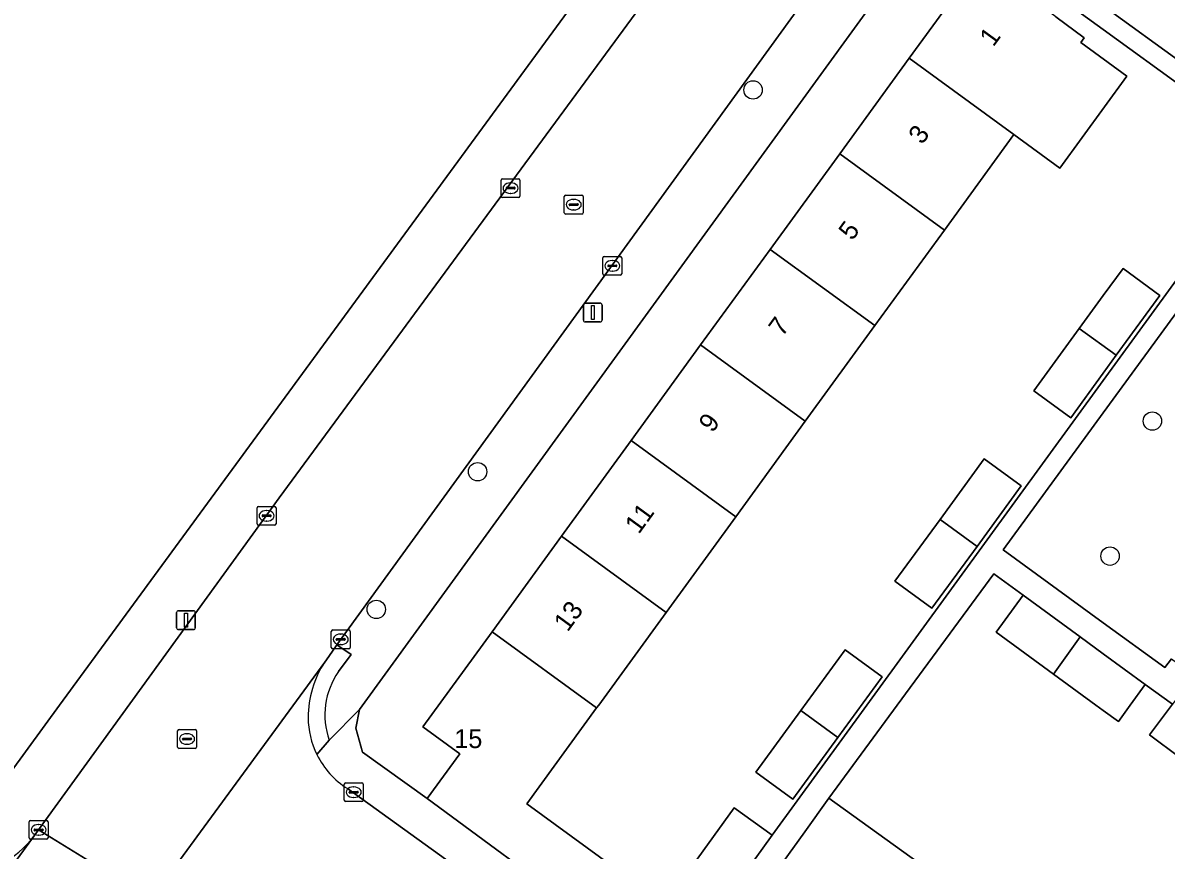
# Model space of a CAD drawing. Extents: x 160102 to 160934, y 382045 to 382923.
# Drawn here: x 160442.6 to 160503.3, y 382492.3 to 382536.2 of the extents above; entities that cross this region are included whole.
import ezdxf

# ---------------------------------------------------------------- set-up
doc = ezdxf.new("R2010")
doc.units = 0
for name, color, linetype in [('IMGEO_Boom', 7, 'Continuous'), ('IMGEO_Erf', 7, 'Continuous'), ('IMGEO_Groenvoorziening', 7, 'Continuous'), ('IMGEO_Kolk', 7, 'Continuous'), ('IMGEO_Lichtmast', 7, 'Continuous'), ('IMGEO_Pand', 7, 'Continuous'), ('IMGEO_Pand_nummerreeks', 7, 'Continuous'), ('IMGEO_Rijbaan_lokaal_open', 7, 'Continuous'), ('IMGEO_Rioolput', 7, 'Continuous'), ('IMGEO_Voetpad_open', 7, 'Continuous')]:
    doc.layers.add(name, color=color, linetype=linetype)

msp = doc.modelspace()

# ---------------------------------------------------------------- linework, layer by layer
at = {"layer": 'IMGEO_Boom'}
for centre in [(160481.4, 382532.653), (160502.606, 382515.077), (160466.767, 382512.388), (160500.358, 382507.908), (160461.385, 382505.081)]:
    msp.add_circle(centre, 0.489, dxfattribs=at)
at = {"layer": 'IMGEO_Erf'}
for points in [[(160466.307, 382588.202), (160494.827, 382565.152), (160500, 382560.972), (160503.073, 382558.488), (160500, 382554.224), (160491.895, 382542.979), (160500, 382537.111), (160512.903, 382527.769), (160513.795, 382534.731), (160510.825, 382535.221), (160511.14, 382537.129), (160511.461, 382539.075), (160514.431, 382538.585), (160515.795, 382546.76), (160513.821, 382547.08), (160514.301, 382550.045), (160516.275, 382549.725), (160519.19, 382547.212), (160517.912, 382530.251), (160515.877, 382500), (160513.04, 382457.812)], [(160476.779, 382489.532), (160480.39, 382494.556), (160482.415, 382493.1), (160487.432, 382500), (160492.218, 382506.559), (160500, 382517.229), (160508.888, 382529.416), (160500, 382535.855), (160491.302, 382542.157), (160460.502, 382499.766), (160460.293, 382498.768), (160460.644, 382497.496), (160464.08, 382495.038), (160465.814, 382497.411), (160463.852, 382498.844), (160467.531, 382503.898), (160471.224, 382508.971), (160474.917, 382514.044), (160478.611, 382519.118), (160482.304, 382524.191), (160485.997, 382529.263), (160489.69, 382534.336), (160493.459, 382539.514)], [(160497.473, 382536.533), (160498.98, 382535.413), (160498.803, 382535.169), (160501.249, 382533.388), (160497.697, 382528.508), (160495.25, 382530.289), (160491.557, 382525.216), (160487.863, 382520.143), (160484.17, 382515.07), (160480.476, 382509.996), (160476.783, 382504.923), (160473.199, 382500), (160473.09, 382499.85), (160469.388, 382494.765), (160474.094, 382491.328)], [(160509.987, 382479.244), (160510.797, 382495.971), (160510.591, 382496.124), (160508.791, 382493.712), (160507.34, 382494.795), (160505.662, 382496.047), (160507.463, 382498.46), (160505.86, 382499.641), (160504.066, 382497.224), (160502.459, 382498.417), (160503.67, 382500.048), (160502.23, 382501.098), (160501.429, 382500), (160500.798, 382499.134), (160500, 382499.716), (160499.611, 382500), (160497.354, 382501.646), (160494.308, 382503.867), (160495.739, 382505.83), (160494.181, 382506.966), (160489.058, 382500), (160485.427, 382495.063), (160490.171, 382491.653)]]:
    msp.add_lwpolyline(points, dxfattribs=at)
for points in [[(160496.312, 382516.689), (160498.726, 382519.998), (160500, 382521.745), (160501.047, 382523.18), (160503.01, 382521.748), (160500.69, 382518.568), (160500, 382517.622), (160498.275, 382515.257)], [(160491.328, 382509.858), (160493.677, 382513.076), (160495.64, 382511.644), (160493.292, 382508.427), (160490.898, 382505.146), (160488.935, 382506.579)], [(160483.941, 382499.711), (160486.29, 382502.929), (160488.253, 382501.497), (160485.905, 382498.28), (160483.511, 382494.999), (160481.548, 382496.432)]]:
    msp.add_lwpolyline(points, close=True, dxfattribs=at)
at = {"layer": 'IMGEO_Groenvoorziening'}
msp.add_lwpolyline([(160440.163, 382493.992), (160444.564, 382500), (160472.07, 382537.55)], dxfattribs=at)
msp.add_lwpolyline([(160512.45, 382521.097), (160506.97, 382525.048), (160500, 382515.515), (160494.685, 382508.245), (160500, 382504.373), (160503.264, 382501.995), (160503.627, 382502.448), (160506.985, 382500), (160510.875, 382497.164), (160511.062, 382500)], close=True, dxfattribs=at)
at = {"layer": 'IMGEO_Kolk'}
for p, q in [((160468.016, 382527.016), (160468.016, 382527.868)), ((160468.091, 382527.942), (160468.943, 382527.942)), ((160468.275, 382527.436), (160468.275, 382527.448)), ((160468.713, 382527.399), (160468.315, 382527.399)), ((160468.318, 382527.485), (160468.716, 382527.485)), ((160468.504, 382527.722), (160468.529, 382527.722)), ((160468.759, 382527.448), (160468.759, 382527.436)), ((160469.017, 382527.868), (160469.017, 382527.016)), ((160468.943, 382526.942), (160468.091, 382526.942)), ((160468.527, 382527.162), (160468.502, 382527.162)), ((160473.421, 382522.89), (160473.421, 382523.742)), ((160473.496, 382523.816), (160474.348, 382523.816)), ((160474.422, 382523.742), (160474.422, 382522.89)), ((160473.68, 382523.31), (160473.68, 382523.322)), ((160474.118, 382523.273), (160473.72, 382523.273)), ((160473.723, 382523.359), (160474.121, 382523.359)), ((160473.909, 382523.596), (160473.934, 382523.596)), ((160474.164, 382523.322), (160474.164, 382523.31)), ((160474.348, 382522.816), (160473.496, 382522.816)), ((160473.932, 382523.036), (160473.907, 382523.036)), ((160455.058, 382509.623), (160455.058, 382510.475)), ((160455.133, 382510.549), (160455.985, 382510.549)), ((160456.059, 382510.475), (160456.059, 382509.623)), ((160455.317, 382510.043), (160455.317, 382510.055)), ((160455.755, 382510.006), (160455.357, 382510.006)), ((160455.36, 382510.092), (160455.758, 382510.092)), ((160455.546, 382510.329), (160455.571, 382510.329)), ((160455.801, 382510.055), (160455.801, 382510.043)), ((160455.985, 382509.549), (160455.133, 382509.549)), ((160455.569, 382509.769), (160455.544, 382509.769)), ((160458.996, 382503.063), (160458.996, 382503.915)), ((160459.071, 382503.989), (160459.923, 382503.989)), ((160459.484, 382503.769), (160459.509, 382503.769)), ((160459.997, 382503.915), (160459.997, 382503.063)), ((160459.255, 382503.483), (160459.255, 382503.495)), ((160459.693, 382503.446), (160459.295, 382503.446)), ((160459.298, 382503.532), (160459.696, 382503.532)), ((160459.507, 382503.209), (160459.482, 382503.209)), ((160459.739, 382503.495), (160459.739, 382503.483)), ((160459.923, 382502.989), (160459.071, 382502.989)), ((160459.76, 382495.876), (160460.612, 382495.876)), ((160459.685, 382494.95), (160459.685, 382495.802)), ((160459.944, 382495.37), (160459.944, 382495.382)), ((160460.382, 382495.333), (160459.984, 382495.333)), ((160459.987, 382495.419), (160460.385, 382495.419)), ((160460.173, 382495.656), (160460.198, 382495.656)), ((160460.428, 382495.382), (160460.428, 382495.37)), ((160460.686, 382495.802), (160460.686, 382494.95)), ((160460.612, 382494.876), (160459.76, 382494.876)), ((160460.196, 382495.096), (160460.171, 382495.096)), ((160442.951, 382492.95), (160442.951, 382493.802)), ((160443.026, 382493.876), (160443.878, 382493.876)), ((160443.21, 382493.37), (160443.21, 382493.382)), ((160443.253, 382493.419), (160443.651, 382493.419)), ((160443.439, 382493.656), (160443.464, 382493.656)), ((160443.694, 382493.382), (160443.694, 382493.37)), ((160443.952, 382493.802), (160443.952, 382492.95)), ((160443.878, 382492.876), (160443.026, 382492.876)), ((160443.648, 382493.333), (160443.25, 382493.333)), ((160443.462, 382493.096), (160443.437, 382493.096))]:
    msp.add_line(p, q, dxfattribs=at)
for points in [[(160468.016, 382527.016), (160468.016, 382527.868)], [(160468.091, 382527.942), (160468.943, 382527.942)], [(160469.017, 382527.868), (160469.017, 382527.016)], [(160468.943, 382526.942), (160468.091, 382526.942)], [(160473.421, 382522.89), (160473.421, 382523.742)], [(160473.496, 382523.816), (160474.348, 382523.816)], [(160474.422, 382523.742), (160474.422, 382522.89)], [(160474.348, 382522.816), (160473.496, 382522.816)], [(160455.058, 382509.623), (160455.058, 382510.475)], [(160455.133, 382510.549), (160455.985, 382510.549)], [(160456.059, 382510.475), (160456.059, 382509.623)], [(160455.985, 382509.549), (160455.133, 382509.549)], [(160458.996, 382503.063), (160458.996, 382503.915)], [(160459.071, 382503.989), (160459.923, 382503.989)], [(160459.997, 382503.915), (160459.997, 382503.063)], [(160459.923, 382502.989), (160459.071, 382502.989)], [(160459.76, 382495.876), (160460.612, 382495.876)], [(160459.685, 382494.95), (160459.685, 382495.802)], [(160460.686, 382495.802), (160460.686, 382494.95)], [(160460.612, 382494.876), (160459.76, 382494.876)], [(160442.951, 382492.95), (160442.951, 382493.802)], [(160443.026, 382493.876), (160443.878, 382493.876)], [(160443.952, 382493.802), (160443.952, 382492.95)], [(160443.878, 382492.876), (160443.026, 382492.876)]]:
    msp.add_lwpolyline(points, dxfattribs=at)
for centre, radius, start, end in [((160468.093, 382527.866), 0.0765, 91.55205, 178.44795), ((160468.093, 382527.866), 0.0765, 91.55205, 178.44795), ((160468.315, 382527.445), 0.0403, 85.87752, 175.75265), ((160468.312, 382527.435), 0.0366, 178.93798, 274.71019), ((160468.716, 382527.442), 0.043, 264.86636, 352.45326), ((160468.72, 382527.447), 0.0386, 1.73085, 96.63898), ((160468.941, 382527.866), 0.0765, 1.55205, 88.44795), ((160468.941, 382527.866), 0.0765, 1.55205, 88.44795), ((160468.093, 382527.018), 0.0765, 181.55205, 268.44795), ((160468.093, 382527.018), 0.0765, 181.55205, 268.44795), ((160468.941, 382527.018), 0.0765, 271.55205, 358.44795), ((160468.941, 382527.018), 0.0765, 271.55205, 358.44795), ((160473.498, 382523.74), 0.0765, 91.55205, 178.44795), ((160473.498, 382523.74), 0.0765, 91.55205, 178.44795), ((160474.346, 382523.74), 0.0765, 1.55205, 88.44795), ((160474.346, 382523.74), 0.0765, 1.55205, 88.44795), ((160473.72, 382523.319), 0.0403, 85.87752, 175.75265), ((160473.717, 382523.309), 0.0366, 178.93798, 274.71019), ((160474.121, 382523.316), 0.043, 264.86636, 352.45326), ((160474.125, 382523.321), 0.0386, 1.73085, 96.63898), ((160473.498, 382522.892), 0.0765, 181.55205, 268.44795), ((160473.498, 382522.892), 0.0765, 181.55205, 268.44795), ((160474.346, 382522.892), 0.0765, 271.55205, 358.44795), ((160474.346, 382522.892), 0.0765, 271.55205, 358.44795), ((160455.135, 382510.473), 0.0765, 91.55205, 178.44795), ((160455.135, 382510.473), 0.0765, 91.55205, 178.44795), ((160455.983, 382510.473), 0.0765, 1.55205, 88.44795), ((160455.983, 382510.473), 0.0765, 1.55205, 88.44795), ((160455.357, 382510.052), 0.0403, 85.87752, 175.75265), ((160455.354, 382510.042), 0.0366, 178.93798, 274.71019), ((160455.758, 382510.049), 0.043, 264.86636, 352.45326), ((160455.762, 382510.054), 0.0386, 1.73085, 96.63898), ((160455.135, 382509.625), 0.0765, 181.55205, 268.44795), ((160455.135, 382509.625), 0.0765, 181.55205, 268.44795), ((160455.983, 382509.625), 0.0765, 271.55205, 358.44795), ((160455.983, 382509.625), 0.0765, 271.55205, 358.44795), ((160459.073, 382503.913), 0.0765, 91.55205, 178.44795), ((160459.073, 382503.913), 0.0765, 91.55205, 178.44795), ((160459.921, 382503.913), 0.0765, 1.55205, 88.44795), ((160459.921, 382503.913), 0.0765, 1.55205, 88.44795), ((160459.295, 382503.492), 0.0403, 85.87752, 175.75265), ((160459.292, 382503.482), 0.0366, 178.93798, 274.71019), ((160459.696, 382503.489), 0.043, 264.86636, 352.45326), ((160459.7, 382503.494), 0.0386, 1.73085, 96.63898), ((160459.073, 382503.065), 0.0765, 181.55205, 268.44795), ((160459.073, 382503.065), 0.0765, 181.55205, 268.44795), ((160459.921, 382503.065), 0.0765, 271.55205, 358.44795), ((160459.921, 382503.065), 0.0765, 271.55205, 358.44795), ((160459.762, 382495.8), 0.0765, 91.55205, 178.44795), ((160459.762, 382495.8), 0.0765, 91.55205, 178.44795), ((160460.61, 382495.8), 0.0765, 1.55205, 88.44795), ((160460.61, 382495.8), 0.0765, 1.55205, 88.44795), ((160459.984, 382495.379), 0.0403, 85.87752, 175.75265), ((160459.981, 382495.369), 0.0366, 178.93798, 274.71019), ((160460.385, 382495.376), 0.043, 264.86636, 352.45326), ((160460.389, 382495.381), 0.0386, 1.73085, 96.63898), ((160459.762, 382494.952), 0.0765, 181.55205, 268.44795), ((160459.762, 382494.952), 0.0765, 181.55205, 268.44795), ((160460.61, 382494.952), 0.0765, 271.55205, 358.44795), ((160460.61, 382494.952), 0.0765, 271.55205, 358.44795), ((160443.028, 382493.8), 0.0765, 91.55205, 178.44795), ((160443.028, 382493.8), 0.0765, 91.55205, 178.44795), ((160443.25, 382493.379), 0.0403, 85.87752, 175.75265), ((160443.655, 382493.381), 0.0386, 1.73085, 96.63898), ((160443.876, 382493.8), 0.0765, 1.55205, 88.44795), ((160443.876, 382493.8), 0.0765, 1.55205, 88.44795), ((160443.028, 382492.952), 0.0765, 181.55205, 268.44795), ((160443.028, 382492.952), 0.0765, 181.55205, 268.44795), ((160443.247, 382493.369), 0.0366, 178.93798, 274.71019), ((160443.651, 382493.376), 0.043, 264.86636, 352.45326), ((160443.876, 382492.952), 0.0765, 271.55205, 358.44795), ((160443.876, 382492.952), 0.0765, 271.55205, 358.44795)]:
    msp.add_arc(centre, radius, start, end, dxfattribs=at)
for centre, major_axis, ratio, start_param, end_param in [((160468.503, 382527.442), (-0.387, 0.002), 0.722429, 4.712389, 7.853982), ((160468.528, 382527.442), (-0.39, 0.002), 0.717154, 1.570796, 4.712389), ((160473.908, 382523.316), (-0.387, 0.002), 0.722429, 4.712389, 7.853982), ((160473.933, 382523.316), (-0.39, 0.002), 0.717154, 1.570796, 4.712389), ((160455.545, 382510.049), (-0.387, 0.002), 0.722429, 4.712389, 7.853982), ((160455.57, 382510.049), (-0.39, 0.002), 0.717154, 1.570796, 4.712389), ((160459.483, 382503.489), (-0.387, 0.002), 0.722429, 4.712389, 7.853982), ((160459.508, 382503.489), (-0.39, 0.002), 0.717154, 1.570796, 4.712389), ((160460.172, 382495.376), (-0.387, 0.002), 0.722429, 4.712389, 7.853982), ((160460.197, 382495.376), (-0.39, 0.002), 0.717154, 1.570796, 4.712389), ((160443.438, 382493.376), (-0.387, 0.002), 0.722429, 4.712389, 7.853982), ((160443.463, 382493.376), (-0.39, 0.002), 0.717154, 1.570796, 4.712389)]:
    msp.add_ellipse(centre, major_axis=major_axis, ratio=ratio, start_param=start_param, end_param=end_param, dxfattribs=at)
at = {"layer": 'IMGEO_Lichtmast'}
for p, q in [((160472.487, 382521.337), (160473.277, 382521.337)), ((160473.277, 382521.337), (160472.487, 382521.337)), ((160472.387, 382520.437), (160472.387, 382521.237)), ((160472.387, 382521.237), (160472.387, 382520.437)), ((160473.377, 382521.237), (160473.377, 382520.437)), ((160473.377, 382520.437), (160473.377, 382521.237)), ((160473.277, 382520.337), (160472.487, 382520.337)), ((160472.487, 382520.337), (160473.277, 382520.337)), ((160450.88, 382505.007), (160451.67, 382505.007)), ((160451.67, 382505.007), (160450.88, 382505.007)), ((160450.78, 382504.107), (160450.78, 382504.907)), ((160450.78, 382504.907), (160450.78, 382504.107)), ((160451.77, 382504.907), (160451.77, 382504.107)), ((160451.77, 382504.107), (160451.77, 382504.907)), ((160451.67, 382504.007), (160450.88, 382504.007)), ((160450.88, 382504.007), (160451.67, 382504.007))]:
    msp.add_line(p, q, dxfattribs=at)
for points in [[(160472.807, 382521.212), (160472.957, 382521.212), (160472.957, 382520.462), (160472.807, 382520.462), (160472.807, 382521.212)], [(160451.2, 382504.882), (160451.35, 382504.882), (160451.35, 382504.132), (160451.2, 382504.132), (160451.2, 382504.882)]]:
    msp.add_lwpolyline(points, dxfattribs=at)
for centre, start, end in [((160472.487, 382521.237), 90, 180), ((160472.487, 382521.237), 90, 180), ((160473.277, 382521.237), 0, 90), ((160473.277, 382521.237), 360, 90), ((160472.487, 382520.437), 180, 270), ((160472.487, 382520.437), 180, 270), ((160473.277, 382520.437), 270, 0), ((160473.277, 382520.437), 270, 0), ((160450.88, 382504.907), 90, 180), ((160450.88, 382504.907), 90, 180), ((160451.67, 382504.907), 0, 90), ((160451.67, 382504.907), 360, 90), ((160450.88, 382504.107), 180, 270), ((160450.88, 382504.107), 180, 270), ((160451.67, 382504.107), 270, 0), ((160451.67, 382504.107), 270, 0)]:
    msp.add_arc(centre, 0.1, start, end, dxfattribs=at)
at = {"layer": 'IMGEO_Pand'}
for points in [[(160498.803, 382535.169), (160498.98, 382535.413), (160497.473, 382536.533), (160493.459, 382539.514), (160489.69, 382534.336), (160495.25, 382530.289), (160497.697, 382528.508), (160501.249, 382533.388)], [(160485.997, 382529.263), (160491.557, 382525.216), (160495.25, 382530.289), (160489.69, 382534.336)], [(160485.997, 382529.263), (160482.304, 382524.191), (160487.863, 382520.143), (160491.557, 382525.216)], [(160478.611, 382519.118), (160484.17, 382515.07), (160487.863, 382520.143), (160482.304, 382524.191)], [(160498.726, 382519.998), (160500.69, 382518.568), (160503.01, 382521.748), (160501.047, 382523.18), (160500, 382521.745)], [(160498.726, 382519.998), (160496.312, 382516.689), (160498.275, 382515.257), (160500, 382517.622), (160500.69, 382518.568)], [(160474.917, 382514.044), (160480.476, 382509.996), (160484.17, 382515.07), (160478.611, 382519.118)], [(160474.917, 382514.044), (160471.224, 382508.971), (160476.783, 382504.923), (160480.476, 382509.996)], [(160493.292, 382508.427), (160495.64, 382511.644), (160493.677, 382513.076), (160491.328, 382509.858)], [(160493.292, 382508.427), (160491.328, 382509.858), (160488.935, 382506.579), (160490.898, 382505.146)], [(160467.531, 382503.898), (160473.09, 382499.85), (160473.199, 382500), (160476.783, 382504.923), (160471.224, 382508.971)], [(160498.773, 382503.619), (160495.739, 382505.83), (160494.308, 382503.867), (160497.354, 382501.646)], [(160467.531, 382503.898), (160463.852, 382498.844), (160465.814, 382497.411), (160464.08, 382495.038), (160472.36, 382488.954), (160474.094, 382491.328), (160469.388, 382494.765), (160473.09, 382499.85)], [(160498.773, 382503.619), (160497.354, 382501.646), (160499.611, 382500), (160500, 382499.716), (160500.798, 382499.134), (160501.429, 382500), (160502.23, 382501.098), (160500, 382502.724)], [(160483.941, 382499.711), (160485.905, 382498.28), (160488.253, 382501.497), (160486.29, 382502.929)], [(160505.86, 382499.641), (160505.377, 382500), (160504.254, 382500.834), (160503.67, 382500.048), (160502.459, 382498.417), (160504.066, 382497.224)], [(160483.941, 382499.711), (160481.548, 382496.432), (160483.511, 382494.999), (160485.905, 382498.28)], [(160485.962, 382485.798), (160490.171, 382491.653), (160485.427, 382495.063), (160484.145, 382493.279), (160481.226, 382489.219)], [(160482.415, 382493.1), (160480.39, 382494.556), (160476.779, 382489.532), (160478.803, 382488.076)]]:
    msp.add_lwpolyline(points, close=True, dxfattribs=at)
at = {"layer": 'IMGEO_Rijbaan_lokaal_open'}
for points in [[(160484.111, 382548.915), (160483.949, 382548.692), (160456.229, 382511.004), (160443.452, 382493.376), (160449.428, 382489.694), (160458.647, 382502.288), (160458.858, 382502.576), (160459.289, 382503.191), (160489.103, 382544.309)], [(160458.647, 382502.288), (160449.428, 382489.694)], [(160489.33, 382474.327), (160476.429, 382483.621), (160473.304, 382485.882), (160459.857, 382495.565)], [(160449.428, 382489.694), (160443.452, 382493.376), (160443.22, 382493.058), (160433.188, 382479.332), (160391.333, 382421.95), (160391.318, 382421.917), (160382.213, 382409.153), (160345.726, 382359.174), (160350.937, 382354.514), (160401.868, 382424.419), (160401.997, 382424.596), (160402.036, 382424.669), (160410.851, 382436.796), (160448.923, 382489.003)], [(160433.188, 382479.332), (160443.22, 382493.058)]]:
    msp.add_lwpolyline(points, dxfattribs=at)
for centre, radius, start, end in [((160463.138, 382499.335), 5.375, 146.67132, 179.99784), ((160462.281, 382499.375), 4.518, 180.50407, 206.31513), ((160462.275, 382499.376), 4.513, 206.35751, 237.60641), ((160438.453, 382496.785), 6.051, 234.7086, 321.98045)]:
    msp.add_arc(centre, radius, start, end, dxfattribs=at)
at = {"layer": 'IMGEO_Rioolput'}
for p, q in [((160471.37, 382526.139), (160471.37, 382526.991)), ((160471.445, 382527.065), (160472.297, 382527.065)), ((160471.858, 382526.845), (160471.883, 382526.845)), ((160472.371, 382526.991), (160472.371, 382526.139)), ((160471.629, 382526.559), (160471.629, 382526.571)), ((160472.067, 382526.522), (160471.669, 382526.522)), ((160471.672, 382526.608), (160472.07, 382526.608)), ((160471.881, 382526.285), (160471.856, 382526.285)), ((160472.113, 382526.571), (160472.113, 382526.559)), ((160472.297, 382526.065), (160471.445, 382526.065)), ((160450.833, 382497.776), (160450.833, 382498.628)), ((160450.908, 382498.702), (160451.76, 382498.702)), ((160451.135, 382498.245), (160451.533, 382498.245)), ((160451.321, 382498.482), (160451.346, 382498.482)), ((160451.834, 382498.628), (160451.834, 382497.776)), ((160451.76, 382497.702), (160450.908, 382497.702)), ((160451.092, 382498.196), (160451.092, 382498.208)), ((160451.53, 382498.159), (160451.132, 382498.159)), ((160451.344, 382497.922), (160451.319, 382497.922)), ((160451.576, 382498.208), (160451.576, 382498.196))]:
    msp.add_line(p, q, dxfattribs=at)
for points in [[(160471.37, 382526.139), (160471.37, 382526.991)], [(160471.445, 382527.065), (160472.297, 382527.065)], [(160472.371, 382526.991), (160472.371, 382526.139)], [(160472.297, 382526.065), (160471.445, 382526.065)], [(160450.833, 382497.776), (160450.833, 382498.628)], [(160450.908, 382498.702), (160451.76, 382498.702)], [(160451.834, 382498.628), (160451.834, 382497.776)], [(160451.76, 382497.702), (160450.908, 382497.702)]]:
    msp.add_lwpolyline(points, dxfattribs=at)
for centre, radius, start, end in [((160471.447, 382526.989), 0.0765, 91.55205, 178.44795), ((160471.447, 382526.989), 0.0765, 91.55205, 178.44795), ((160472.295, 382526.989), 0.0765, 1.55205, 88.44795), ((160472.295, 382526.989), 0.0765, 1.55205, 88.44795), ((160471.669, 382526.568), 0.0403, 85.87752, 175.75265), ((160471.666, 382526.558), 0.0366, 178.93798, 274.71019), ((160472.07, 382526.565), 0.043, 264.86636, 352.45326), ((160472.074, 382526.57), 0.0386, 1.73085, 96.63898), ((160471.447, 382526.141), 0.0765, 181.55205, 268.44795), ((160471.447, 382526.141), 0.0765, 181.55205, 268.44795), ((160472.295, 382526.141), 0.0765, 271.55205, 358.44795), ((160472.295, 382526.141), 0.0765, 271.55205, 358.44795), ((160450.91, 382498.626), 0.0765, 91.55205, 178.44795), ((160450.91, 382498.626), 0.0765, 91.55205, 178.44795), ((160451.132, 382498.205), 0.0403, 85.87752, 175.75265), ((160451.537, 382498.207), 0.0386, 1.73085, 96.63898), ((160451.758, 382498.626), 0.0765, 1.55205, 88.44795), ((160451.758, 382498.626), 0.0765, 1.55205, 88.44795), ((160450.91, 382497.778), 0.0765, 181.55205, 268.44795), ((160450.91, 382497.778), 0.0765, 181.55205, 268.44795), ((160451.129, 382498.195), 0.0366, 178.93798, 274.71019), ((160451.533, 382498.202), 0.043, 264.86636, 352.45326), ((160451.758, 382497.778), 0.0765, 271.55205, 358.44795), ((160451.758, 382497.778), 0.0765, 271.55205, 358.44795)]:
    msp.add_arc(centre, radius, start, end, dxfattribs=at)
for centre, major_axis, ratio, start_param, end_param in [((160471.857, 382526.565), (-0.387, 0.002), 0.722429, 4.712389, 7.853982), ((160471.882, 382526.565), (-0.39, 0.002), 0.717154, 1.570796, 4.712389), ((160451.32, 382498.202), (-0.387, 0.002), 0.722429, 4.712389, 7.853982), ((160451.345, 382498.202), (-0.39, 0.002), 0.717154, 1.570796, 4.712389)]:
    msp.add_ellipse(centre, major_axis=major_axis, ratio=ratio, start_param=start_param, end_param=end_param, dxfattribs=at)
at = {"layer": 'IMGEO_Voetpad_open'}
for points in [[(160481.629, 382550.609), (160473.289, 382539.215), (160472.07, 382537.55), (160444.564, 382500), (160440.163, 382493.992)], [(160443.22, 382493.058), (160443.452, 382493.376), (160456.229, 382511.004), (160483.949, 382548.692)], [(160489.103, 382544.309), (160459.289, 382503.191), (160460.043, 382502.691), (160459.374, 382501.781)], [(160512.903, 382527.769), (160500, 382537.111), (160491.895, 382542.979), (160491.676, 382542.675), (160491.302, 382542.157), (160500, 382535.855), (160508.888, 382529.416), (160500, 382517.229), (160492.218, 382506.559), (160487.432, 382500), (160482.415, 382493.1), (160478.803, 382488.076)], [(160458.886, 382498.142), (160460.502, 382499.766), (160491.302, 382542.157)], [(160503.627, 382502.448), (160503.264, 382501.995), (160500, 382504.373), (160494.685, 382508.245), (160500, 382515.515), (160506.97, 382525.048)], [(160481.226, 382489.219), (160484.145, 382493.279), (160485.427, 382495.063), (160489.058, 382500), (160494.181, 382506.966), (160495.739, 382505.83), (160498.773, 382503.619), (160500, 382502.724), (160502.23, 382501.098), (160503.67, 382500.048)], [(160459.374, 382501.781), (160460.043, 382502.691), (160459.289, 382503.191), (160458.858, 382502.576), (160458.647, 382502.288)], [(160464.08, 382495.038), (160460.644, 382497.496), (160460.293, 382498.768), (160460.502, 382499.766), (160458.886, 382498.142), (160458.231, 382497.372)], [(160458.231, 382497.372), (160458.886, 382498.142)], [(160459.857, 382495.565), (160473.304, 382485.882), (160474.996, 382487.042), (160472.36, 382488.954), (160464.08, 382495.038)]]:
    msp.add_lwpolyline(points, dxfattribs=at)
for centre, radius, start, end in [((160463.138, 382499.335), 5.375, 146.67132, 179.99784), ((160462.699, 382499.483), 4.042, 145.35233, 199.37176), ((160462.699, 382499.483), 4.042, 145.35233, 199.37176), ((160462.281, 382499.375), 4.518, 180.50407, 206.31513), ((160462.275, 382499.376), 4.513, 206.35751, 237.60641), ((160438.453, 382496.785), 6.051, 234.7086, 321.98045)]:
    msp.add_arc(centre, radius, start, end, dxfattribs=at)

# ---------------------------------------------------------------- texts
at = {"layer": 'IMGEO_Pand_nummerreeks'}
for s, rotation, p in [('1', 53.94398, (160494.16, 382534.903)), ('3', 53.94566, (160490.38, 382529.712)), ('5', 53.94566, (160486.668, 382524.612)), ('7', 53.94566, (160482.956, 382519.513)), ('9', 53.94566, (160479.244, 382514.414)), ('11', 53.94566, (160475.328, 382509.036)), ('13', 53.94566, (160471.549, 382503.844))]:
    msp.add_text(s, height=1, rotation=rotation, dxfattribs=at).set_placement(p)
msp.add_text('15', height=1, dxfattribs=at).set_placement((160465.529, 382497.718))

doc.saveas('drawing.dxf')
